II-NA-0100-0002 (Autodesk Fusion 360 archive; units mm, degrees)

design "II-NA-0100-0003" references "Digitus_DN-651107_LAN-Switch 19.5mm", "3M Screw", "1 ports ethernet", "15EDGKM-5.08-02P-14-00AH", "LED"
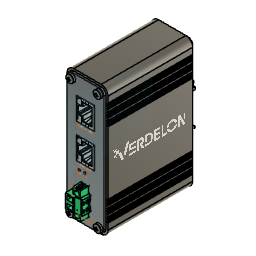
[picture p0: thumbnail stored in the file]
sketch "Sketch1" plane through (0, 0, 0) normal (0, 1, 0) x axis (1, 0, 0)
  line L1 (25, 0) -> (5, 0)
  line L2 (30, -90) -> (30, -5)
  line L3 (5, -95) -> (25, -95)
  line L4 (0, -5) -> (0, -90)
  arc A1 centre (5, -90) radius 5 clockwise from (5, -95) to (0, -90)
  arc A2 centre (25, -90) radius 5 clockwise from (30, -90) to (25, -95)
  arc A3 centre (5, -5) radius 5 clockwise from (0, -5) to (5, 0)
  arc A4 centre (25, -5) radius 5 clockwise from (25, 0) to (30, -5)
  point P1 (0, 0)
  point P2 (0, 0)
  point P4 (0, -95)
  point P3 (30, 0)
  horizontal L1
  vertical L2
  horizontal L3
  vertical L4
  coincident P1 P2
  coincident P4 L3
  coincident P4 L4
  tangent L3 A1
  tangent L4 A1
  tangent L2 A2
  tangent L3 A2
  equal A1 A2
  coincident P2 L1
  coincident P2 L4
  tangent L1 A3
  tangent L4 A3
  equal A1 A3
  coincident P3 L1
  coincident P3 L2
  tangent L1 A4
  tangent L2 A4
  equal A1 A4
  dimension "d1" distance P2 P4 = 95
  dimension "d2" distance P2 P3 = 30
  dimension "d3" radius A1 = 5
extrude "Extrude1" new body sketch "Sketch1" along normal blind 65
sketch "Sketch2" plane through (0, 0, 0) normal (0, -1, 0) x axis (1, 0, 0)
  line L1 (5, 95) -> (25, 95)
  line L2 (0, 5) -> (0, 90)
  line L3 (25, 0) -> (5, 0)
  line L4 (30, 90) -> (30, 5)
  line L5 (1.5, 5) -> (1.5, 90)
  line L6 (25, 1.5) -> (5, 1.5)
  line L7 (28.5, 90) -> (28.5, 5)
  line L8 (5, 93.5) -> (25, 93.5)
  line L9 (0, 5) -> (0, 90)
  line L10 (25, 0) -> (5, 0)
  line L11 (30, 90) -> (30, 5)
  line L12 (5, 95) -> (25, 95)
  arc A1 centre (25, 90) radius 5 clockwise from (25, 95) to (30, 90)
  arc A2 centre (5, 90) radius 5 clockwise from (0, 90) to (5, 95)
  arc A3 centre (5, 5) radius 5 clockwise from (5, 0) to (0, 5)
  arc A4 centre (25, 5) radius 5 clockwise from (30, 5) to (25, 0)
  arc A5 centre (5, 5) radius 3.5 clockwise from (5, 1.5) to (1.5, 5)
  arc A6 centre (25, 5) radius 3.5 clockwise from (28.5, 5) to (25, 1.5)
  arc A7 centre (25, 90) radius 3.5 clockwise from (25, 93.5) to (28.5, 90)
  arc A8 centre (5, 90) radius 3.5 clockwise from (1.5, 90) to (5, 93.5)
  arc A9 centre (5, 5) radius 5 clockwise from (5, 0) to (0, 5)
  arc A10 centre (25, 5) radius 5 clockwise from (30, 5) to (25, 0)
  arc A11 centre (25, 90) radius 5 clockwise from (25, 95) to (30, 90)
  arc A12 centre (5, 90) radius 5 clockwise from (0, 90) to (5, 95)
  dimension "d6" = -1.5
  dimension "d7" distance L2 = 0
extrude "Extrude2" cut sketch "Sketch2" against normal blind 1.5
sketch "Sketch3" plane through (0, 65, 0) normal (0, 1, 0) x axis (-1, 0, 0)
  line L1 (-30, 5) -> (-30, 90)
  line L2 (-5, 0) -> (-25, 0)
  line L3 (0, 90) -> (0, 5)
  line L4 (-25, 95) -> (-5, 95)
  line L5 (-28.5, 5) -> (-28.5, 90)
  line L6 (-5, 1.5) -> (-25, 1.5)
  line L7 (-1.5, 90) -> (-1.5, 5)
  line L8 (-25, 93.5) -> (-5, 93.5)
  line L9 (-30, 5) -> (-30, 90)
  line L10 (-5, 0) -> (-25, 0)
  line L11 (0, 90) -> (0, 5)
  line L12 (-25, 95) -> (-5, 95)
  arc A1 centre (-25, 90) radius 5 clockwise from (-30, 90) to (-25, 95)
  arc A2 centre (-25, 5) radius 5 clockwise from (-25, 0) to (-30, 5)
  arc A3 centre (-5, 5) radius 5 clockwise from (0, 5) to (-5, 0)
  arc A4 centre (-5, 90) radius 5 clockwise from (-5, 95) to (0, 90)
  arc A5 centre (-25, 5) radius 3.5 clockwise from (-25, 1.5) to (-28.5, 5)
  arc A6 centre (-5, 5) radius 3.5 clockwise from (-1.5, 5) to (-5, 1.5)
  arc A7 centre (-5, 90) radius 3.5 clockwise from (-5, 93.5) to (-1.5, 90)
  arc A8 centre (-25, 90) radius 3.5 clockwise from (-28.5, 90) to (-25, 93.5)
  arc A9 centre (-25, 5) radius 5 clockwise from (-25, 0) to (-30, 5)
  arc A10 centre (-5, 5) radius 5 clockwise from (0, 5) to (-5, 0)
  arc A11 centre (-5, 90) radius 5 clockwise from (-5, 95) to (0, 90)
  arc A12 centre (-25, 90) radius 5 clockwise from (-30, 90) to (-25, 95)
  dimension "d10" = -1.5
  dimension "d11" distance L1 = 0
extrude "Extrude3" cut sketch "Sketch3" against normal blind 1.5
sketch "Sketch4" plane through (0, 1.5, 0) normal (0, -1, 0) x axis (1, 0, 0)
  line L1 (25, 93.5) -> (5, 93.5)
  line L2 (28.5, 5) -> (28.5, 90)
  line L3 (5, 1.5) -> (25, 1.5)
  line L4 (1.5, 90) -> (1.5, 5)
  line L5 (0, 5) -> (0, 90)
  line L6 (25, 0) -> (5, 0)
  line L7 (30, 90) -> (30, 5)
  line L8 (5, 95) -> (25, 95)
  line L9 (-15.934, 47.5) -> (1.5, 47.5)
  line L10 (15, 105) -> (15, 93.5)
  line L11 (0.5, 85.5) -> (0, 85.5)
  line L12 (0.5, 84.5) -> (0.5, 85.5)
  line L13 (0, 84.5) -> (0.5, 84.5)
  line L14 (0, 85.5) -> (0, 84.5)
  line L15 (0, 84) -> (0, 83)
  line L16 (0, 83) -> (0.5, 83)
  line L17 (0.5, 84) -> (0, 84)
  line L18 (0.5, 83) -> (0.5, 84)
  line L19 (0, 82.5) -> (0, 81.5)
  line L20 (0, 81.5) -> (0.5, 81.5)
  line L21 (0.5, 82.5) -> (0, 82.5)
  line L22 (0.5, 81.5) -> (0.5, 82.5)
  line L23 (0, 79) -> (0.5, 79)
  line L24 (0, 77) -> (0, 76)
  line L25 (0, 78.5) -> (0, 77.5)
  line L26 (0.5, 78.5) -> (0, 78.5)
  line L27 (0.5, 80) -> (0, 80)
  line L28 (0, 76) -> (0.5, 76)
  line L29 (0.5, 76) -> (0.5, 77)
  line L30 (0, 80) -> (0, 79)
  line L31 (0.5, 77) -> (0, 77)
  line L32 (0, 77.5) -> (0.5, 77.5)
  line L33 (0.5, 77.5) -> (0.5, 78.5)
  line L34 (0.5, 79) -> (0.5, 80)
  line L35 (0, 73.5) -> (0.5, 73.5)
  line L36 (0, 71.5) -> (0, 70.5)
  line L37 (0, 73) -> (0, 72)
  line L38 (0.5, 73) -> (0, 73)
  line L39 (0.5, 74.5) -> (0, 74.5)
  line L40 (0, 70.5) -> (0.5, 70.5)
  line L41 (0.5, 70.5) -> (0.5, 71.5)
  line L42 (0, 74.5) -> (0, 73.5)
  line L43 (0.5, 71.5) -> (0, 71.5)
  line L44 (0, 72) -> (0.5, 72)
  line L45 (0.5, 72) -> (0.5, 73)
  line L46 (0.5, 73.5) -> (0.5, 74.5)
  line L47 (0, 23.5) -> (0, 24.5)
  line L48 (0.5, 17.5) -> (0.5, 16.5)
  line L49 (0.5, 19) -> (0.5, 18)
  line L50 (0, 20.5) -> (0, 21.5)
  line L51 (0, 16) -> (0.5, 16)
  line L52 (0.5, 11) -> (0, 11)
  line L53 (0.5, 12) -> (0.5, 11)
  line L54 (0, 12) -> (0.5, 12)
  line L55 (0.5, 15) -> (0, 15)
  line L56 (0, 15) -> (0, 16)
  line L57 (0, 17.5) -> (0.5, 17.5)
  line L58 (0, 19) -> (0.5, 19)
  line L59 (0.5, 16) -> (0.5, 15)
  line L60 (0, 11) -> (0, 12)
  line L61 (0, 22) -> (0, 23)
  line L62 (0.5, 18) -> (0, 18)
  line L63 (0, 13.5) -> (0.5, 13.5)
  line L64 (0.5, 23) -> (0.5, 22)
  line L65 (0.5, 10.5) -> (0.5, 9.5)
  line L66 (0, 10.5) -> (0.5, 10.5)
  line L67 (0.5, 23.5) -> (0, 23.5)
  line L68 (0.5, 12.5) -> (0, 12.5)
  line L69 (0.5, 21.5) -> (0.5, 20.5)
  line L70 (0.5, 16.5) -> (0, 16.5)
  line L71 (0, 12.5) -> (0, 13.5)
  line L72 (0, 16.5) -> (0, 17.5)
  line L73 (0, 24.5) -> (0.5, 24.5)
  line L74 (0.5, 24.5) -> (0.5, 23.5)
  line L75 (0, 21.5) -> (0.5, 21.5)
  line L76 (0.5, 9.5) -> (0, 9.5)
  line L77 (0.5, 13.5) -> (0.5, 12.5)
  line L78 (0, 9.5) -> (0, 10.5)
  line L79 (0, 18) -> (0, 19)
  line L80 (0.5, 22) -> (0, 22)
  line L81 (0.5, 20.5) -> (0, 20.5)
  line L82 (0, 23) -> (0.5, 23)
  line L83 (30, 76) -> (29.5, 76)
  line L84 (30, 70.5) -> (29.5, 70.5)
  line L85 (29.5, 73.5) -> (29.5, 74.5)
  line L86 (30, 84.5) -> (29.5, 84.5)
  line L87 (30, 73) -> (30, 72)
  line L88 (30, 83) -> (29.5, 83)
  line L89 (30, 72) -> (29.5, 72)
  line L90 (30, 73.5) -> (29.5, 73.5)
  line L91 (29.5, 83) -> (29.5, 84)
  line L92 (29.5, 77) -> (30, 77)
  line L93 (30, 71.5) -> (30, 70.5)
  line L94 (30, 78.5) -> (30, 77.5)
  line L95 (29.5, 73) -> (30, 73)
  line L96 (29.5, 82.5) -> (30, 82.5)
  line L97 (30, 81.5) -> (29.5, 81.5)
  line L98 (29.5, 84) -> (30, 84)
  line L99 (29.5, 77.5) -> (29.5, 78.5)
  line L100 (30, 79) -> (29.5, 79)
  line L101 (29.5, 84.5) -> (29.5, 85.5)
  line L102 (30, 77) -> (30, 76)
  line L103 (30, 74.5) -> (30, 73.5)
  line L104 (29.5, 79) -> (29.5, 80)
  line L105 (29.5, 81.5) -> (29.5, 82.5)
  line L106 (30, 80) -> (30, 79)
  line L107 (29.5, 85.5) -> (30, 85.5)
  line L108 (30, 85.5) -> (30, 84.5)
  line L109 (29.5, 76) -> (29.5, 77)
  line L110 (30, 84) -> (30, 83)
  line L111 (29.5, 71.5) -> (30, 71.5)
  line L112 (29.5, 78.5) -> (30, 78.5)
  line L113 (29.5, 70.5) -> (29.5, 71.5)
  line L114 (30, 82.5) -> (30, 81.5)
  line L115 (29.5, 80) -> (30, 80)
  line L116 (29.5, 74.5) -> (30, 74.5)
  line L117 (30, 77.5) -> (29.5, 77.5)
  line L118 (29.5, 72) -> (29.5, 73)
  line L119 (30, 17.5) -> (29.5, 17.5)
  line L120 (29.5, 23.5) -> (30, 23.5)
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  point P22 (1.5, 47.5)
  point P24 (15, 93.5)
  point P26 (0, 85.5)
  point P81 (0, 9.5)
  point P27 (0.5, 85.5)
  point P73 (0.5, 9.5)
  point P28 (0.5, 84.5)
  point P67 (0.5, 10.5)
  point P29 (0, 84.5)
  point P89 (0, 10.5)
  point P30 (0, 83)
  point P91 (0, 12)
  point P31 (0, 84)
  point P86 (0, 11)
  point P32 (0.5, 83)
  point P65 (0.5, 12)
  point P33 (0.5, 84)
  point P77 (0.5, 11)
  point P34 (0, 81.5)
  point P70 (0, 13.5)
  point P35 (0, 82.5)
  point P68 (0, 12.5)
  point P36 (0.5, 81.5)
  point P80 (0.5, 13.5)
  point P37 (0.5, 82.5)
  point P82 (0.5, 12.5)
  point P38 (0, 79)
  point P83 (0, 16)
  point P39 (0.5, 79)
  point P76 (0.5, 16)
  point P40 (0.5, 80)
  point P74 (0.5, 15)
  point P41 (0, 76)
  point P71 (0, 19)
  point P42 (0, 77)
  point P62 (0, 18)
  point P43 (0.5, 77)
  point P63 (0.5, 18)
  point P44 (0, 77.5)
  point P93 (0, 17.5)
  point P45 (0, 78.5)
  point P92 (0, 16.5)
  point P46 (0.5, 78.5)
  point P90 (0.5, 16.5)
  point P47 (0, 80)
  point P96 (0, 15)
  point P48 (0.5, 76)
  point P95 (0.5, 19)
  point P49 (0.5, 77.5)
  point P97 (0.5, 17.5)
  point P50 (0, 73.5)
  point P87 (0, 21.5)
  point P51 (0.5, 73.5)
  point P88 (0.5, 21.5)
  point P52 (0.5, 74.5)
  point P94 (0.5, 20.5)
  point P53 (0, 70.5)
  point P66 (0, 24.5)
  point P54 (0, 71.5)
  point P64 (0, 23.5)
  point P55 (0.5, 71.5)
  point P78 (0.5, 23.5)
  point P56 (0, 72)
  point P72 (0, 23)
  point P57 (0, 73)
  point P75 (0, 22)
  point P58 (0.5, 73)
  point P69 (0.5, 22)
  point P59 (0, 74.5)
  point P79 (0, 20.5)
  point P60 (0.5, 70.5)
  point P84 (0.5, 24.5)
  point P61 (0.5, 72)
  point P85 (0.5, 23)
  point P106 (30, 85.5)
  point P121 (29.5, 85.5)
  point P122 (29.5, 84.5)
  point P118 (30, 84.5)
  point P120 (30, 83)
  point P119 (30, 84)
  point P123 (29.5, 83)
  point P126 (29.5, 84)
  point P125 (30, 81.5)
  point P124 (30, 82.5)
  point P100 (29.5, 81.5)
  point P98 (29.5, 82.5)
  point P102 (30, 79)
  point P99 (29.5, 79)
  point P101 (29.5, 80)
  point P131 (30, 76)
  point P129 (30, 77)
  point P127 (29.5, 77)
  point P130 (30, 77.5)
  point P133 (30, 78.5)
  point P128 (29.5, 78.5)
  point P132 (30, 80)
  point P113 (29.5, 76)
  point P116 (29.5, 77.5)
  point P112 (30, 73.5)
  point P117 (29.5, 73.5)
  point P115 (29.5, 74.5)
  point P114 (30, 70.5)
  point P111 (30, 71.5)
  point P105 (29.5, 71.5)
  point P108 (30, 72)
  point P104 (30, 73)
  point P103 (29.5, 73)
  point P109 (30, 74.5)
  point P110 (29.5, 70.5)
  point P107 (29.5, 72)
  point P169 (30, 18)
  point P134 (29.5, 18)
  point P138 (30, 23.5)
  point P166 (29.5, 12)
  point P139 (30, 24.5)
  point P160 (29.5, 10.5)
  point P140 (30, 12.5)
  point P135 (29.5, 22)
  point P147 (30, 13.5)
  point P136 (30, 19)
  point P155 (30, 23)
  point P148 (29.5, 9.5)
  point P162 (29.5, 15)
  point P168 (30, 22)
  point P157 (29.5, 16)
  point P141 (29.5, 11)
  point P165 (29.5, 23.5)
  point P167 (30, 20.5)
  point P151 (29.5, 13.5)
  point P143 (30, 9.5)
  point P152 (29.5, 12.5)
  point P150 (30, 16)
  point P145 (29.5, 24.5)
  point P142 (29.5, 23)
  point P164 (30, 11)
  point P149 (30, 21.5)
  point P146 (29.5, 21.5)
  point P154 (30, 10.5)
  point P144 (29.5, 16.5)
  point P153 (30, 12)
  point P158 (30, 16.5)
  point P156 (30, 17.5)
  point P163 (29.5, 20.5)
  point P161 (29.5, 19)
  point P159 (30, 15)
  point P137 (29.5, 17.5)
  midpoint L4 P22
  perpendicular L4 L9
  midpoint L1 P24
  perpendicular L8 L10
  horizontal L11
  vertical L12
  horizontal L13
  vertical L14
  coincident L5 P26
  symmetric L9 P26 P81
  symmetric L9 P27 P73
  symmetric L9 P28 P67
  symmetric L9 P29 P89
  symmetric L9 P30 P91
  symmetric L9 P31 P86
  symmetric L9 P32 P65
  symmetric L9 P33 P77
  symmetric L9 P34 P70
  symmetric L9 P35 P68
  symmetric L9 P36 P80
  symmetric L9 P37 P82
  symmetric L9 P38 P83
  symmetric L9 P39 P76
  symmetric L9 P40 P74
  symmetric L9 P41 P71
  symmetric L9 P42 P62
  symmetric L9 P43 P63
  symmetric L9 P44 P93
  symmetric L9 P45 P92
  symmetric L9 P46 P90
  symmetric L9 P47 P96
  symmetric L9 P48 P95
  symmetric L9 P49 P97
  symmetric L9 P50 P87
  symmetric L9 P51 P88
  symmetric L9 P52 P94
  symmetric L9 P53 P66
  symmetric L9 P54 P64
  symmetric L9 P55 P78
  symmetric L9 P56 P72
  symmetric L9 P57 P75
  symmetric L9 P58 P69
  symmetric L9 P59 P79
  symmetric L9 P60 P84
  symmetric L9 P61 P85
  symmetric L10 P26 P106
  symmetric L10 P27 P121
  symmetric L10 P28 P122
  symmetric L10 P29 P118
  symmetric L10 P30 P120
  symmetric L10 P31 P119
  symmetric L10 P32 P123
  symmetric L10 P33 P126
  symmetric L10 P34 P125
  symmetric L10 P35 P124
  symmetric L10 P36 P100
  symmetric L10 P37 P98
  symmetric L10 P38 P102
  symmetric L10 P39 P99
  symmetric L10 P40 P101
  symmetric L10 P41 P131
  symmetric L10 P42 P129
  symmetric L10 P43 P127
  symmetric L10 P44 P130
  symmetric L10 P45 P133
  symmetric L10 P46 P128
  symmetric L10 P47 P132
  symmetric L10 P48 P113
  symmetric L10 P49 P116
  symmetric L10 P50 P112
  symmetric L10 P51 P117
  symmetric L10 P52 P115
  symmetric L10 P53 P114
  symmetric L10 P54 P111
  symmetric L10 P55 P105
  symmetric L10 P56 P108
  symmetric L10 P57 P104
  symmetric L10 P58 P103
  symmetric L10 P59 P109
  symmetric L10 P60 P110
  symmetric L10 P61 P107
  symmetric L10 P62 P169
  symmetric L10 P63 P134
  symmetric L10 P64 P138
  symmetric L10 P65 P166
  symmetric L10 P66 P139
  symmetric L10 P67 P160
  symmetric L10 P68 P140
  symmetric L10 P69 P135
  symmetric L10 P70 P147
  symmetric L10 P71 P136
  symmetric L10 P72 P155
  symmetric L10 P73 P148
  symmetric L10 P74 P162
  symmetric L10 P75 P168
  symmetric L10 P76 P157
  symmetric L10 P77 P141
  symmetric L10 P78 P165
  symmetric L10 P79 P167
  symmetric L10 P80 P151
  symmetric L10 P81 P143
  symmetric L10 P82 P152
  symmetric L10 P83 P150
  symmetric L10 P84 P145
  symmetric L10 P85 P142
  symmetric L10 P86 P164
  symmetric L10 P87 P149
  symmetric L10 P88 P146
  symmetric L10 P89 P154
  symmetric L10 P90 P144
  symmetric L10 P91 P153
  symmetric L10 P92 P158
  symmetric L10 P93 P156
  symmetric L10 P94 P163
  symmetric L10 P95 P161
  symmetric L10 P96 P159
  symmetric L10 P97 P137
  dimension "d14" distance P26 P29 = 1
  dimension "d15" distance P26 P27 = 0.5
  dimension "d24" distance L9 L40 = 23
  dimension "d18" R-Pattern1-uDistance = 0
  dimension "d19" R-Pattern1-vDistance = -3
  dimension "d22" R-Pattern2-uDistance = 0
  dimension "d23" R-Pattern2-vDistance = -11
extrude "Extrude4" cut sketch "Sketch4" against normal blind 64
sketch "Sketch10" plane through (0, 0, 0) normal (0, -1, 0) x axis (1, 0, 0)
  line L1 (5, 93.5) -> (25, 93.5)
  line L2 (1.5, 5) -> (1.5, 90)
  line L3 (25, 1.5) -> (5, 1.5)
  line L4 (28.5, 90) -> (28.5, 5)
  line L5 (15, 47.5) -> (15, 93.5)
  line L6 (15, 47.5) -> (1.5, 47.5)
  line L7 (21.58, 80.5) -> (8.42, 80.5)
  line L8 (21.58, 64.09) -> (21.58, 80.5)
  line L9 (8.42, 64.09) -> (21.58, 64.09)
  line L10 (8.42, 80.5) -> (8.42, 64.09)
  line L11 (8.42, 55.5) -> (8.42, 39.09)
  line L12 (8.42, 39.09) -> (21.58, 39.09)
  line L13 (21.58, 39.09) -> (21.58, 55.5)
  line L14 (21.58, 55.5) -> (8.42, 55.5)
  line L15 (18.075, 22) -> (11.925, 22)
  line L16 (18.075, 14.12) -> (18.075, 22)
  line L17 (11.925, 14.12) -> (18.075, 14.12)
  line L18 (11.925, 22) -> (11.925, 14.12)
  line L19 (10, 18.06) -> (11.925, 18.06)
  line L20 (15, 15.6742) -> (15, 14.12)
  arc A1 centre (5, 90) radius 3.5 clockwise from (1.5, 90) to (5, 93.5)
  arc A2 centre (5, 5) radius 3.5 clockwise from (5, 1.5) to (1.5, 5)
  arc A3 centre (25, 5) radius 3.5 clockwise from (28.5, 5) to (25, 1.5)
  arc A4 centre (25, 90) radius 3.5 clockwise from (25, 93.5) to (28.5, 90)
  circle C1 centre (10.42, 34.09) radius 0.75
  circle C2 centre (14.42, 34.09) radius 0.75
  circle C3 centre (5, 90) radius 1.5
  circle C4 centre (25, 90) radius 1.5
  circle C5 centre (5, 5) radius 1.5
  circle C6 centre (25, 5) radius 1.5
  circle C7 centre (15.1004, 11.1) radius 1.3
  circle C8 centre (15.1004, 25.02) radius 1.3
  point P14 (15, 93.5)
  point P15 (1.5, 47.5)
  point P36 (11.925, 18.06)
  point P39 (15, 14.12)
  point P17 (8.42, 80.5)
  point P20 (8.42, 64.09)
  point P18 (21.58, 80.5)
  point P25 (10.42, 34.09)
  point P31 (11.925, 22)
  point P34 (11.925, 14.12)
  point P32 (18.075, 22)
  point P35 (15.1004, 11.1)
  midpoint L1 P14
  perpendicular L1 L5
  midpoint L2 P15
  perpendicular L2 L6
  horizontal L7
  vertical L8
  horizontal L9
  vertical L10
  symmetric L5 L8 L10
  concentric A1 C3
  horizontal L15
  vertical L16
  horizontal L17
  vertical L18
  symmetric L5 L16 L18
  midpoint L18 P36
  perpendicular L18 L19
  symmetric C7 L19 C8
  midpoint L17 P39
  perpendicular L17 L20
  dimension "d99" distance P17 P20 = 16.41
  dimension "d100" distance P17 P18 = 13.16
  dimension "d105" diameter C1 = 1.5
  dimension "d110" distance L6 L14 = 8
  dimension "d111" distance L12 P25 = 5
  dimension "d112" distance L11 P25 = 2
  dimension "d113" diameter C3 = 3
  dimension "d122" distance P31 P34 = 7.88
  dimension "d123" distance P31 P32 = 6.15
  dimension "d124" diameter C7 = 2.6
  dimension "d125" distance L17 P35 = 3.02
  dimension "d126" distance L6 L15 = 25.5
  dimension "d127" distance P34 P35 = 3.1754
  dimension "d103" R-Pattern1-uDistance = 0
  dimension "d104" R-Pattern1-vDistance = -25
  dimension "d108" R-Pattern2-uDistance = 4
  dimension "d109" R-Pattern2-vDistance = 0
  dimension "d116" R-Pattern3-uDistance = 20
  dimension "d117" R-Pattern3-vDistance = 0
  dimension "d120" R-Pattern4-uDistance = 0
  dimension "d121" R-Pattern4-vDistance = -85
extrude "Extrude7" cut sketch "Sketch10" profile of L5 L6 L7 L8 L9 L10 L11 L12 L13 L14 C1 C2 C3 C4 C5 C6 L15 L16 L17 L18 C7 C8 against normal blind 1
shell "Shell2" innerThickness 1
component_insert "Component Insert3"
component_insert "Component Insert10"
position "Position2"
sketch "Sketch9" plane through (0, 0, 0) normal (-1, 0, 0) x axis (0, -1, 0)
  line L1 (-1.5, 24.5) -> (-63.5, 24.5)
  line L2 (-1.5, 70.5) -> (-1.5, 24.5)
  line L3 (-63.5, 70.5) -> (-1.5, 70.5)
  line L4 (-63.5, 24.5) -> (-63.5, 70.5)
joint "Assemble3" alignAngle 0 alignOffsetX 0 alignOffsetY 0 alignOffsetZ 1.5
rectangular_pattern "00000000-0000-0000-0000-000000000000" uSpaceDistance -4 vSpaceDistance 0
component_insert "Component Insert15"
component_insert "Component Insert16"
position "Position3"
rectangular_pattern "00000000-0000-0000-0000-000000000000" uSpaceDistance 25 vSpaceDistance 0
component_insert "Component Insert17"
position "Position4"
rectangular_pattern "00000000-0000-0000-0000-000000000000" uSpaceDistance 20 vSpaceDistance 0
rectangular_pattern "00000000-0000-0000-0000-000000000000" uSpaceDistance -85 vSpaceDistance 0
decal "Decal1"
decal "Decal2"
sketch "Sketch11" plane through (0, 0, 0) normal (0, -1, 0) x axis (1, 0, 0)
  dimension "d151" = 1.5
  dimension "d152" = 1.5
  dimension "d153" = 1.5
  dimension "d154" = 1
  dimension "d155" = 1
  dimension "d156" = 1.5
  dimension "d157" = 1.5
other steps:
joint_origin "JointOrigin3"

design "15EDGKM-5.08-02P-14-00AH"
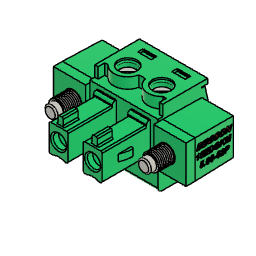
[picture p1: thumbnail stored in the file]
description: STEP AP214
part number: 15EDGKM-5.08-02P-14-00AH

design "3M Screw"
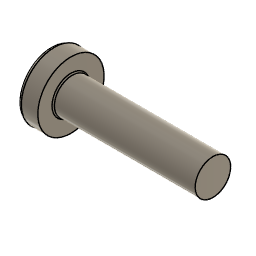
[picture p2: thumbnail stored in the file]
description: STEP AP214
part number: 3M Screw

design "Digitus_DN-651107_LAN-Switch 19.5mm"
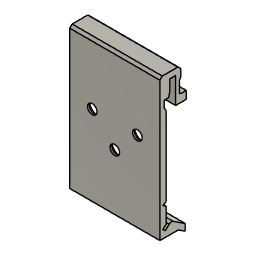
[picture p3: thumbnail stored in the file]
description: STEP AP214
part number: Digitus_DN-651107_LAN-Switch 19.5mm

design "1 ports ethernet"
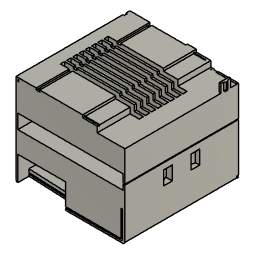
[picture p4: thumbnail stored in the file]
description: STEP AP214
part number: 1 ports ethernet

design "LED"
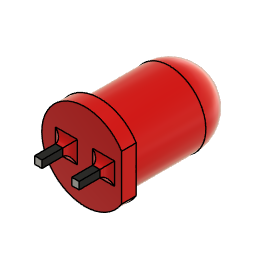
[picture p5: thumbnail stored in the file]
description: STEP AP214
part number: LED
